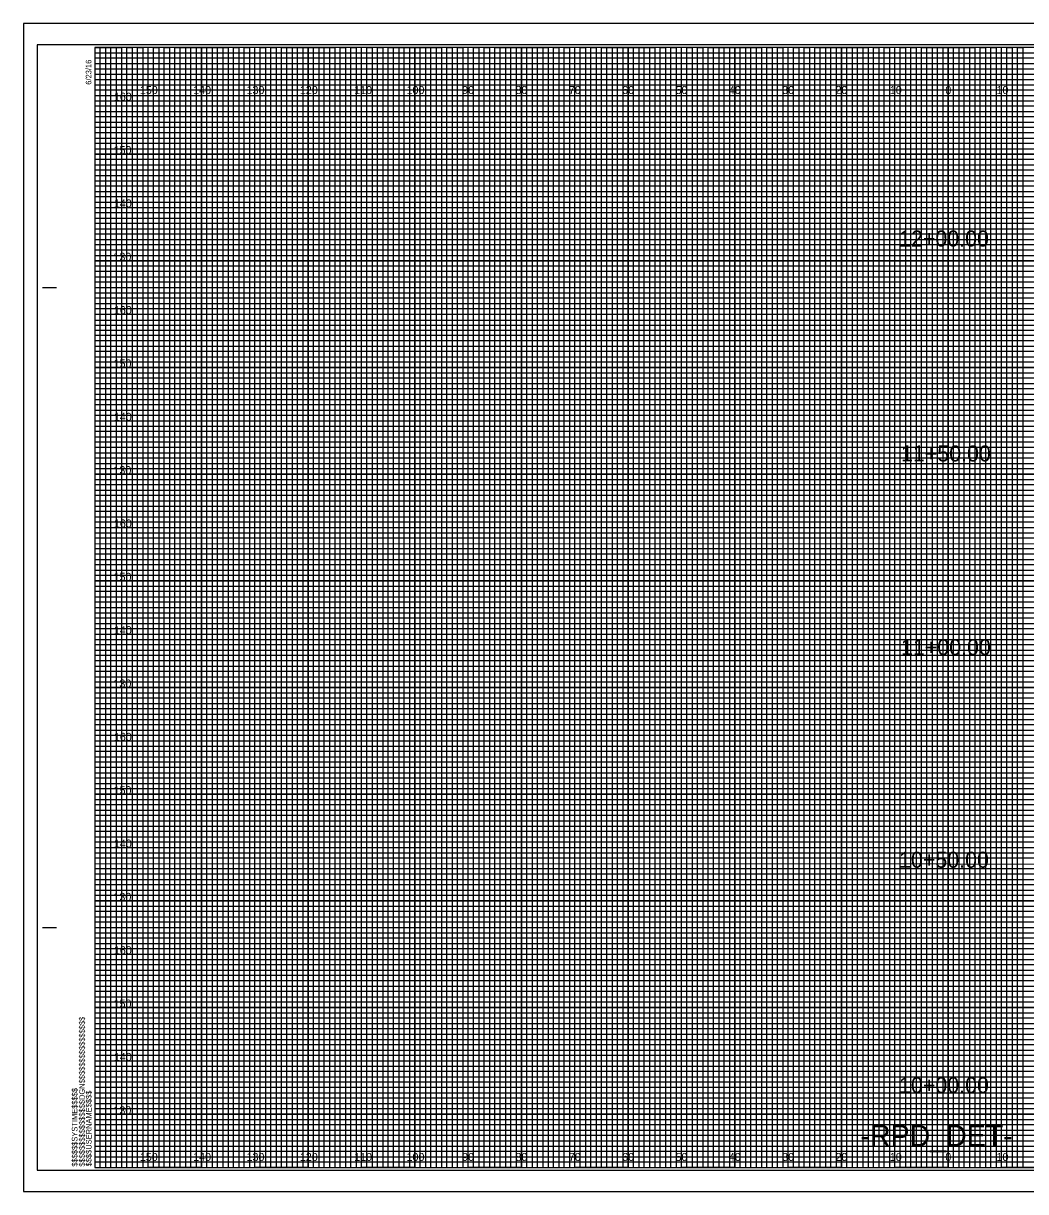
# Model space of a CAD drawing. Extents: x -13 to 323, y -5 to 434.
# Drawn here: x -13.4 to 174.5, y -4.5 to 214.5 of the extents above; entities that cross this region are included whole.
import ezdxf

# ---------------------------------------------------------------- set-up
doc = ezdxf.new("R2010")
doc.units = 0
for name, color, linetype in [('Exist Cross Section Cell', 7, 'Continuous'), ('Exist XS Center Line Elevation Label', 7, 'Continuous'), ('Exist XS Ground Line', 7, 'Continuous'), ('Prop CMT Pvmt Course 1', 7, 'Continuous'), ('Prop CMT Pvmt Course 3', 7, 'Continuous'), ('Prop CMT Pvmt Surface', 7, 'Continuous'), ('Prop CMT Pvmt Surface Shoulder', 7, 'Continuous'), ('Prop CMT Shld Paved Course 1', 7, 'Continuous'), ('Prop CMT Shld Paved Course 2', 7, 'Continuous'), ('Prop CMT Shld Paved Course 3', 7, 'Continuous'), ('Prop CMT Slope Grass', 7, 'Continuous'), ('Prop CMT Subgrade Earthwork', 7, 'Continuous'), ('Scratch_Level_1', 7, 'Continuous')]:
    doc.layers.add(name, color=color, linetype=linetype)

msp = doc.modelspace()

# ---------------------------------------------------------------- linework, layer by layer
at = {"layer": 'Exist XS Center Line Elevation Label'}
for points in [[(0, 210), (5, 210), (5, 0), (15, 0), (15, 210), (25, 210), (25, 0), (35, 0), (35, 210), (45, 210), (45, 0), (55, 0), (55, 210), (65, 210), (65, 0), (75, 0), (75, 210), (85, 210), (85, 0), (95, 0), (95, 210), (105, 210), (105, 0), (115, 0), (115, 210), (125, 210), (125, 0), (135, 0), (135, 210), (145, 210), (145, 0), (155, 0), (155, 210), (165, 210), (165, 0), (175, 0)], [(0, 205), (275, 205)], [(0, 185), (320, 185), (320, 195), (0, 195)], [(0, 165), (320, 165), (320, 175), (0, 175)], [(0, 145), (320, 145), (320, 155), (0, 155)], [(0, 125), (320, 125), (320, 135), (0, 135)], [(0, 105), (320, 105), (320, 115), (0, 115)], [(0, 85), (320, 85), (320, 95), (0, 95)], [(0, 65), (320, 65), (320, 75), (0, 75)], [(0, 45), (320, 45), (320, 55), (0, 55)], [(0, 25), (320, 25), (320, 35), (0, 35)], [(0, 5), (320, 5), (320, 15), (0, 15)]]:
    msp.add_lwpolyline(points, dxfattribs=at)
at = {"layer": 'Exist XS Ground Line'}
for p, q in [((10, 210), (0, 210)), ((10, 0), (10, 210)), ((30, 210), (20, 210)), ((20, 210), (20, 0)), ((30, 0), (30, 210)), ((50, 210), (40, 210)), ((40, 210), (40, 0)), ((50, 0), (50, 210)), ((70, 210), (60, 210)), ((60, 210), (60, 0)), ((70, 0), (70, 210)), ((90, 210), (80, 210)), ((80, 210), (80, 0)), ((90, 0), (90, 210)), ((110, 210), (100, 210)), ((100, 210), (100, 0)), ((110, 0), (110, 210)), ((130, 210), (120, 210)), ((120, 210), (120, 0)), ((130, 0), (130, 210)), ((150, 210), (140, 210)), ((140, 210), (140, 0)), ((150, 0), (150, 210)), ((170, 210), (160, 210)), ((160, 210), (160, 0)), ((170, 0), (170, 210)), ((20, 0), (10, 0)), ((40, 0), (30, 0)), ((60, 0), (50, 0)), ((80, 0), (70, 0)), ((100, 0), (90, 0)), ((120, 0), (110, 0)), ((140, 0), (130, 0)), ((160, 0), (150, 0)), ((180, 0), (170, 0))]:
    msp.add_line(p, q, dxfattribs=at)
for points in [[(0, 200), (320, 200), (320, 190), (0, 190)], [(0, 180), (320, 180), (320, 170), (0, 170)], [(0, 160), (320, 160), (320, 150), (0, 150)], [(0, 140), (320, 140), (320, 130), (0, 130)], [(0, 120), (320, 120), (320, 110), (0, 110)], [(0, 100), (320, 100), (320, 90), (0, 90)], [(0, 80), (320, 80), (320, 70), (0, 70)], [(0, 60), (320, 60), (320, 50), (0, 50)], [(0, 40), (320, 40), (320, 30), (0, 30)], [(0, 20), (320, 20), (320, 10), (0, 10)]]:
    msp.add_lwpolyline(points, dxfattribs=at)
at = {"layer": 'Prop CMT Pvmt Course 3'}
msp.add_lwpolyline([(-13.4, -4.5), (323.3, -4.5), (323.3, 214.5), (-13.4, 214.5)], close=True, dxfattribs=at)
at = {"layer": 'Prop CMT Pvmt Surface'}
for p, q in [((10, 0), (10, 210)), ((20, 0), (20, 210)), ((30, 0), (30, 210)), ((40, 0), (40, 210)), ((50, 0), (50, 210)), ((60, 0), (60, 210)), ((70, 0), (70, 210)), ((80, 0), (80, 210)), ((90, 0), (90, 210)), ((100, 0), (100, 210)), ((110, 0), (110, 210)), ((120, 0), (120, 210)), ((130, 0), (130, 210)), ((140, 0), (140, 210)), ((150, 0), (150, 210)), ((160, 0), (160, 210)), ((170, 0), (170, 210)), ((0, 200), (320, 200)), ((0, 190), (320, 190)), ((0, 180), (320, 180)), ((0, 170), (320, 170)), ((0, 160), (320, 160)), ((0, 150), (320, 150)), ((0, 140), (320, 140)), ((0, 130), (320, 130)), ((0, 120), (320, 120)), ((0, 110), (320, 110)), ((0, 100), (320, 100)), ((0, 90), (320, 90)), ((0, 80), (320, 80)), ((0, 70), (320, 70)), ((0, 60), (320, 60)), ((0, 50), (320, 50)), ((0, 40), (320, 40)), ((0, 30), (320, 30)), ((0, 20), (320, 20)), ((0, 10), (320, 10))]:
    msp.add_line(p, q, dxfattribs=at)
at = {"layer": 'Prop CMT Pvmt Surface Shoulder'}
for p, q in [((323.3, 214.5), (-13.4, 214.5)), ((-13.4, 214.5), (-13.4, -4.5)), ((-13.4, -4.5), (323.3, -4.5))]:
    msp.add_line(p, q, dxfattribs=at)
at = {"layer": 'Prop CMT Shld Paved Course 1'}
for p, q in [((0, 209), (260, 209)), ((260, 207.98), (0, 207.98)), ((0, 207.98), (0, 207)), ((0, 207), (260, 207)), ((260, 205.89), (0, 205.89)), ((0, 205.89), (0, 204)), ((0, 204), (320, 204))]:
    msp.add_line(p, q, dxfattribs=at)
for points in [[(0, 203), (270, 203), (320, 203), (320, 202), (0, 202)], [(0, 201), (320, 201), (320, 199), (0, 199)], [(0, 198), (320, 198), (320, 197), (0, 196.98)], [(0, 196), (320, 196), (320, 194), (0, 194)], [(0, 193), (320, 193), (320, 192), (0, 192)], [(0, 191), (320, 191), (320, 189), (0, 189)], [(0, 188), (320, 188), (320, 187), (0, 187)], [(0, 186), (320, 186), (320, 184), (0, 184)], [(0, 183), (320, 183), (320, 182), (0, 182)], [(0, 181), (320, 181), (320, 179), (0, 179)], [(0, 178), (320, 178), (320, 177), (0, 177)], [(0, 176), (320, 176), (320, 173.95), (320, 173), (320, 172), (0, 172)], [(0, 174), (320, 174), (320, 173), (0, 173)], [(0, 171), (320, 171), (320, 169), (0, 169.03)], [(0, 169.03), (320, 169), (320, 168), (0, 168)], [(0, 167), (320, 167), (320, 166), (0, 166)], [(0, 164), (320, 164), (320, 163), (0, 163)], [(0, 162), (320, 162), (320, 161), (0, 161)], [(-0.07, 158.89), (320, 158.89), (320, 157.88), (-0.07, 157.88)], [(0, 157), (320, 157), (320, 156), (0, 156)], [(0, 154), (320, 154), (320, 153), (0, 153)], [(0, 152), (320, 152), (320, 151), (0, 151)], [(0, 149), (320, 149), (320, 148), (0, 148)], [(0, 147), (320, 147), (320, 146), (0, 146)], [(0, 144), (320, 144), (320, 143), (0, 143)], [(0, 142), (320, 142), (320, 141), (0, 141)], [(0, 139), (320, 139), (319.99, 137.98), (0, 138)], [(0, 137), (320, 137), (320, 136), (0, 136)], [(0, 134), (320, 134), (320, 133), (0, 133)], [(0, 132), (320, 132), (320, 131), (0, 131)], [(0, 129), (320, 129), (320, 128), (0, 128)], [(0, 127), (320, 127), (320, 126), (0, 126)], [(0, 124), (320, 124), (320, 123), (0, 123)], [(0, 122), (320, 122), (320, 121), (0, 121)], [(0, 119), (320, 119), (320, 118), (0, 118)], [(0, 116.99), (320.07, 116.91), (320, 116), (0, 116)], [(0, 114), (320, 114), (320, 113), (0, 113)], [(0, 112), (320, 112), (320, 111), (0, 111)], [(0, 109), (320, 109), (320, 108), (0, 108)], [(0, 107), (320, 107), (320, 106), (0, 106)], [(0, 104), (320, 104), (320, 103), (0, 103)], [(0, 102), (320, 102), (320, 101), (0, 101)], [(0, 99), (320, 99), (320, 98), (0, 98)], [(0, 97), (320, 97), (320, 96), (0, 96)], [(0, 94), (320, 94), (320, 93), (0, 93)], [(0, 92), (320, 92), (320, 91), (0, 91)], [(0, 89), (320, 89), (320, 88), (0, 88)], [(0, 87), (320, 87), (320, 86), (0, 86)], [(0, 84), (320, 84), (320, 83), (0, 83)], [(0, 82), (320, 82), (320, 81), (0, 81)], [(0, 79), (320, 79), (319.99, 77.98), (0, 78)], [(0, 77), (320, 77), (320, 76), (0, 76)], [(0, 74), (320, 74), (320, 73), (0, 73)], [(0, 72), (320, 72), (320, 71), (0, 71)], [(0, 69), (320, 69), (320, 68), (0, 68)], [(0, 67), (320, 67), (320, 66), (0, 66)], [(0, 64), (320, 64), (320, 63), (0, 63)], [(0, 62), (320, 62), (320, 61), (0, 61)], [(0, 59), (320, 59), (320, 58), (0, 58)], [(0, 56.99), (320.07, 56.91), (320, 56), (0, 56)], [(0, 54), (320, 54), (320, 53), (0, 53)], [(0, 52), (320, 52), (320, 51), (0, 51)], [(0, 49), (320, 49), (320, 48), (0, 48)], [(0, 47), (320, 47), (320, 46), (0, 46)], [(0, 44), (320, 44), (320, 43), (0, 43)], [(0, 42), (320, 42), (320, 41), (0, 41)], [(0, 39), (320, 39), (320, 38), (0, 38)], [(0, 37), (320, 37), (320, 36), (0, 36)], [(0, 34), (320, 34), (320, 33), (0, 33)], [(0, 32), (320, 32), (320, 31), (0, 31)], [(0, 29), (320, 29), (320, 28), (0, 28)], [(0, 27), (320, 27), (320, 26), (0, 26)], [(0, 24), (320, 24), (320, 23), (0, 23)], [(0, 22), (320, 22), (320, 21), (0, 21)], [(0, 19), (320, 19), (320, 18), (0, 18)], [(0, 17), (320, 17), (320, 16), (0, 16)], [(0, 14), (320, 14), (320, 13), (0, 13)], [(0, 12), (320, 12), (320, 11), (0, 11)], [(0, 9), (320, 9), (320, 8), (0, 8)], [(0, 7), (320, 7), (320, 6), (0, 6)], [(0, 4), (320, 4), (320, 3), (0, 3)], [(0, 2), (320, 2), (320, 1), (0, 1)]]:
    msp.add_lwpolyline(points, dxfattribs=at)
at = {"layer": 'Prop CMT Shld Paved Course 2'}
for p, q in [((-9.8, 165), (-7.3, 165)), ((-9.7, 165), (-7.2, 165)), ((-9.8, 45), (-7.3, 45)), ((-9.7, 45), (-7.2, 45)), ((0, 0), (0, 0)), ((0, 0), (0, 0)), ((0, 0), (0, 0)), ((0, 0), (0, 0)), ((0, 0), (0, 0)), ((0, 0), (0, 0)), ((0, 0), (0, 0))]:
    msp.add_line(p, q, dxfattribs=at)
msp.add_lwpolyline([(320, 210), (0, 210), (0, 0), (320, 0)], close=True, dxfattribs=at)
at = {"layer": 'Prop CMT Shld Paved Course 3'}
for points in [[(0, 0), (1, 0), (1, 210), (2, 210), (2, 0)], [(2, 0), (3, 0), (3, 210), (4, 210), (4, 0)], [(5, 0), (6, 0), (6, 210), (7, 210), (7, 0)], [(7, 0), (8, 0), (8, 210), (9, 210), (9, 0)], [(10, 0), (11, 0), (11, 210), (12, 210), (12, 0)], [(12, 0), (13, 0), (13, 210), (14, 210), (14, 0)], [(15, 0), (16, 0), (16, 210), (17, 210), (17, 0)], [(17, 0), (18, 0), (18, 210), (19, 210), (19, 0)], [(20, 0), (21, 0), (21, 210), (22, 210), (22, 0)], [(22, 0), (23, 0), (23, 210), (24, 210), (24, 0)], [(25, 0), (26, 0), (26, 210), (27, 210), (27, 0)], [(27, 0), (28, 0), (28, 210), (29, 210), (29, 0)], [(30, 0), (31, 0), (31, 210), (32, 210), (32, 0)], [(32, 0), (33, 0), (33, 210), (34, 210), (34, 0)], [(35, 0), (36, 0), (36, 210), (37, 210), (37, 0)], [(37, 0), (38, 0), (38, 210), (39, 210), (39, 0)], [(40, 0), (41, 0), (41, 210), (42, 210), (42, 0)], [(42, 0), (43, 0), (43, 210), (44, 210), (44, 0)], [(45, 0), (46, 0), (46, 210), (47, 210), (47, 0)], [(47, 0), (48, 0), (48, 210), (49, 210), (49, 0)], [(50, 0), (51, 0), (51, 210), (52, 210), (52, 0)], [(52, 0), (53, 0), (53, 210), (54, 210), (54, 0)], [(55, 0), (56, 0), (56, 210), (57, 210), (57, 0)], [(57, 0), (58, 0), (58, 210), (59, 210), (59, 0)], [(60, 0), (61, 0), (61, 210), (62, 210), (62, 0)], [(62, 0), (63, 0), (63, 210), (64, 210), (64, 0)], [(65, 0), (66, 0), (66, 210), (67, 210), (67, 0)], [(67, 0), (68, 0), (68, 210), (69, 210), (69, 0)], [(70, 0), (71, 0), (71, 210), (72, 210), (72, 0)], [(72, 0), (73, 0), (73, 210), (74, 210), (74, 0)], [(75, 0), (76, 0), (76, 210), (77, 210), (77, 0)], [(77, 0), (78, 0), (78, 210), (79, 210), (79, 0)], [(80, 0), (81, 0), (81, 210), (82, 210), (82, 0)], [(82, 0), (83, 0), (83, 210), (84, 210), (84, 0)], [(85, 0), (86, 0), (86, 210), (87, 210), (87, 0)], [(87, 0), (88, 0), (88, 210), (89, 210), (89, 0)], [(90, 0), (91, 0), (91, 210), (92, 210), (92, 0)], [(92, 0), (93, 0), (93, 210), (94, 210), (94, 0)], [(95, 0), (96, 0), (96, 210), (97, 210), (97, 0)], [(97, 0), (98, 0), (98, 210), (99, 210), (99, 0)], [(100, 0), (101, 0), (101, 210), (102, 210), (102, 0)], [(102, 0), (103, 0), (103, 210), (104, 210), (104, 0)], [(105, 0), (106, 0), (106, 210), (107, 210), (107, 0)], [(107, 0), (108, 0), (108, 210), (109, 210), (109, 0)], [(110, 0), (111, 0), (111, 210), (112, 210), (112, 0)], [(112, 0), (113, 0), (113, 210), (114, 210), (114, 0)], [(115, 0), (116, 0), (116, 210), (117, 210), (117, 0)], [(117, 0), (118, 0), (118, 210), (119, 210), (119, 0)], [(120, 0), (121, 0), (121, 210), (122, 210), (122, 0)], [(122, 0), (123, 0), (123, 210), (124, 210), (124, 0)], [(125, 0), (126, 0), (126, 210), (127, 210), (127, 0)], [(127, 0), (128, 0), (128, 210), (129, 210), (129, 0)], [(130, 0), (131, 0), (131, 210), (132, 210), (132, 0)], [(132, 0), (133, 0), (133, 210), (134, 210), (134, 0)], [(135, 0), (136, 0), (136, 210), (137, 210), (137, 0)], [(137, 0), (138, 0), (138, 210), (139, 210), (139, 0)], [(140, 0), (141, 0), (141, 210), (142, 210), (142, 0)], [(142, 0), (143, 0), (143, 210), (144, 210), (144, 0)], [(145, 0), (146, 0), (146, 210), (147, 210), (147, 0)], [(147, 0), (148, 0), (148, 210), (149, 210), (149, 0)], [(150, 0), (151, 0), (151, 210), (152, 210), (152, 0)], [(152, 0), (153, 0), (153, 210), (154, 210), (154, 0)], [(155, 0), (156, 0), (156, 210), (157, 210), (157, 0)], [(157, 0), (158, 0), (158, 210), (159, 210), (159, 0)], [(160, 0), (161, 0), (161, 210), (162, 210), (162, 0)], [(162, 0), (163, 0), (163, 210), (164, 210), (164, 0)], [(165, 0), (166, 0), (166, 210), (167, 210), (167, 0)], [(167, 0), (168, 0), (168, 210), (169, 210), (169, 0)], [(170, 0), (171, 0), (171, 210), (172, 210), (172, 0)], [(172, 0), (173, 0), (173, 210), (174, 210), (174, 0)]]:
    msp.add_lwpolyline(points, dxfattribs=at)
at = {"layer": 'Prop CMT Subgrade Earthwork'}
msp.add_lwpolyline([(-10.8, -0.5), (322.4, -0.5), (322.4, 210.5), (-10.8, 210.5)], close=True, dxfattribs=at)

# ---------------------------------------------------------------- texts
at = {"layer": 'Exist Cross Section Cell'}
for s, p in [('150', (8.44, 201.25)), ('140', (18.44, 201.25)), ('130', (28.44, 201.25)), ('120', (38.44, 201.25)), ('110', (48.62, 201.25)), ('100', (58.44, 201.25)), ('90', (68.86, 201.25)), ('80', (78.86, 201.25)), ('70', (88.86, 201.25)), ('60', (98.86, 201.25)), ('50', (108.86, 201.25)), ('40', (118.86, 201.25)), ('30', (128.86, 201.25)), ('20', (138.86, 201.25)), ('10', (149.04, 201.25)), ('0', (159.45, 201.25)), ('0', (159.45, 201.25)), ('10', (169.04, 201.25)), ('150', (8.44, 1.25)), ('140', (18.44, 1.25)), ('130', (28.44, 1.25)), ('120', (38.44, 1.25)), ('110', (48.62, 1.25)), ('100', (58.44, 1.25)), ('90', (68.86, 1.25)), ('80', (78.86, 1.25)), ('70', (88.86, 1.25)), ('60', (98.86, 1.25)), ('50', (108.86, 1.25)), ('40', (118.86, 1.25)), ('30', (128.86, 1.25)), ('20', (138.86, 1.25)), ('10', (149.04, 1.25)), ('0', (159.45, 1.25)), ('0', (159.45, 1.25)), ('10', (169.04, 1.25))]:
    msp.add_text(s, height=1.5, dxfattribs=at).set_placement(p)
at = {"layer": 'Prop CMT Pvmt Course 1'}
for s, p in [('160', (3.57, 200)), ('150', (3.52, 190)), ('140', (3.57, 180)), ('130', (3.49, 170)), ('160', (3.57, 160)), ('150', (3.52, 150)), ('140', (3.57, 140)), ('130', (3.49, 130)), ('160', (3.57, 120)), ('150', (3.52, 110)), ('140', (3.57, 100)), ('130', (3.49, 90)), ('160', (3.57, 80)), ('150', (3.52, 70)), ('140', (3.57, 60)), ('130', (3.49, 50)), ('160', (3.57, 40)), ('150', (3.52, 30)), ('140', (3.57, 20)), ('130', (3.49, 10))]:
    msp.add_text(s, height=1.5, dxfattribs=at).set_placement(p)
at = {"layer": 'Prop CMT Shld Paved Course 2'}
for s, p in [('6/23/16', (-0.65, 203)), ('$$$$$$$$$$$$$$$$DGN$$$$$$$$$$$$$$$$', (-1.88, 0.18)), ('$$$$$$SYSTIME$$$$$', (-3.26, 0.18)), ('$$$$USERNAME$$$$', (-0.62, 0.23))]:
    msp.add_text(s, height=1.05, rotation=90, dxfattribs=at).set_placement(p)
at = {"layer": 'Prop CMT Slope Grass'}
for s, p in [('12+00.00', (150.77, 172.67)), ('11+50.00', (151.13, 132.38)), ('11+00.00', (151.13, 96.07)), ('10+50.00', (150.77, 56.22)), ('10+00.00', (150.77, 13.97))]:
    msp.add_text(s, height=3, dxfattribs=at).set_placement(p)
at = {"layer": 'Scratch_Level_1'}
msp.add_text('-RPD_DET-', height=4, dxfattribs=at).set_placement((143.54, 4))

doc.saveas('drawing.dxf')
